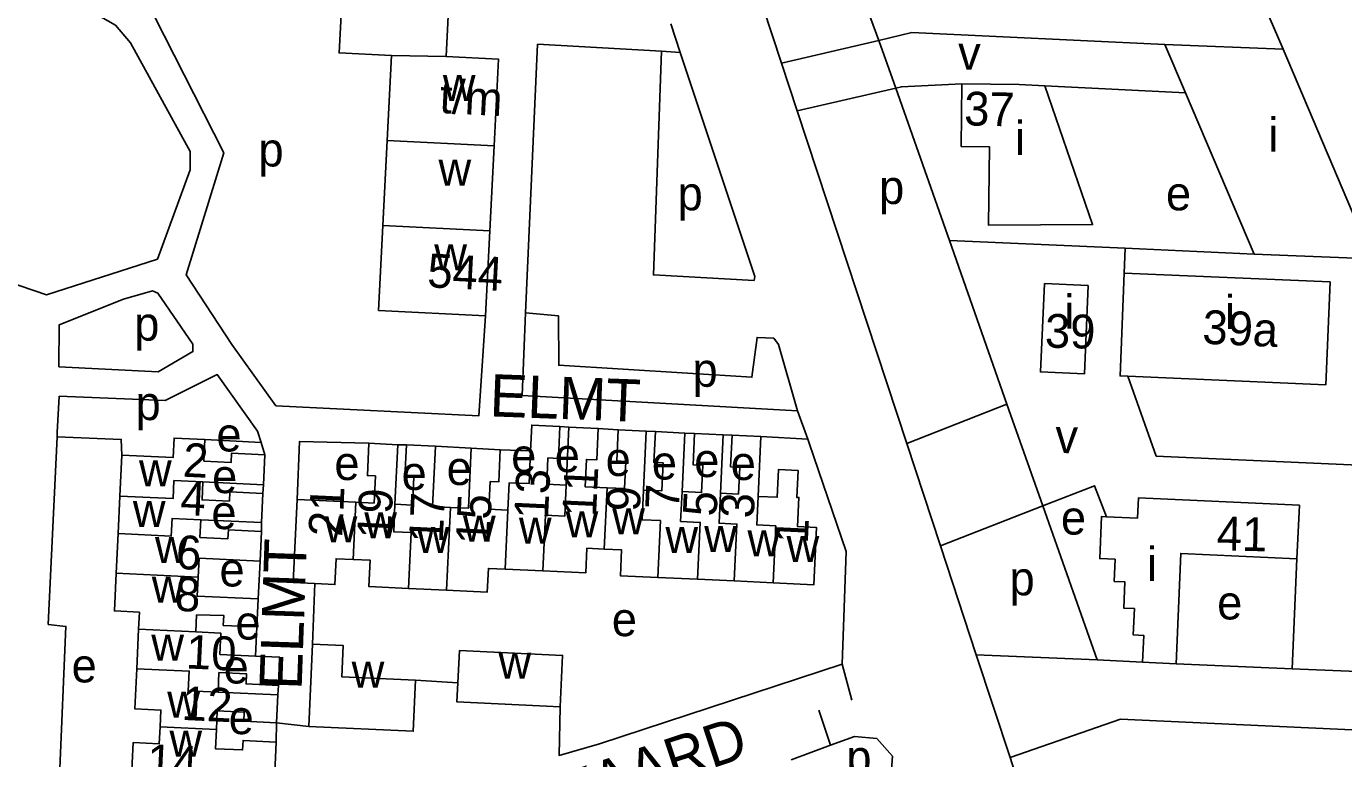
# Model space of a CAD drawing. Extents: x 163026 to 166241, y 382475 to 384501.
# Drawn here: x 164720.8 to 164876.6, y 383908.9 to 383995.6 of the extents above; entities that cross this region are included whole.
import ezdxf

# ---------------------------------------------------------------- set-up
doc = ezdxf.new("R2010")
doc.units = 0
for name, color, linetype in [('BLT_Basislijn', 7, 'Continuous'), ('BLT_Bebouwing', 7, 'Continuous'), ('BLT_Centroide', 7, 'Continuous'), ('BLT_Huisnummer', 7, 'Continuous'), ('BLT_Huisnummer_ tussenligend', 7, 'Continuous'), ('BLT_Huisnummer_reeks', 7, 'Continuous'), ('BLT_Onderverdeling_panden', 7, 'Continuous'), ('BLT_Straatnaam', 7, 'Continuous')]:
    doc.layers.add(name, color=color, linetype=linetype)

msp = doc.modelspace()

# ---------------------------------------------------------------- linework, layer by layer
at = {"layer": 'BLT_Basislijn'}
for p, q in [((164821.62, 383993.91), (164814.91, 384012.33)), ((164869.4, 383992.88), (164861.88, 384010.26)), ((164797, 383995.86), (164798.12, 383992.49)), ((164821.62, 383993.91), (164810.1, 383991.21)), ((164821.62, 383993.91), (164823.61, 383988.26)), ((164795.92, 383992.62), (164798.12, 383992.49)), ((164811.96, 383985.56), (164823.61, 383988.26)), ((164823.61, 383988.26), (164829.95, 383970.22)), ((164841.23, 383988.53), (164857.86, 383987.7)), ((164829.95, 383970.22), (164836.76, 383950.87)), ((164829.95, 383970.22), (164850.73, 383969.31)), ((164850.61, 383966.35), (164850.73, 383969.31)), ((164850.73, 383969.31), (164866, 383968.63)), ((164854.39, 383944.72), (164851.07, 383954.18)), ((164812.01, 383950.1), (164813.21, 383946.73)), ((164824.91, 383946.22), (164836.76, 383950.87)), ((164836.76, 383950.87), (164840.99, 383938.84)), ((164783.9, 383948.24), (164784.96, 383948.17)), ((164788.43, 383948.01), (164790.8, 383947.85)), ((164794.12, 383947.69), (164795.19, 383947.62)), ((164798.67, 383947.46), (164799.82, 383947.42)), ((164803.21, 383947.26), (164804.26, 383947.2)), ((164807.66, 383947.04), (164813.21, 383946.73)), ((164748.58, 383946.34), (164741.93, 383946.7)), ((164749.02, 383944.89), (164748.58, 383946.34)), ((164764.73, 383946.08), (164765.75, 383946.06)), ((164769.19, 383945.9), (164773.41, 383945.65)), ((164776.85, 383945.49), (164780.43, 383945.34)), ((164854.39, 383944.72), (164882.61, 383943.48)), ((164748.79, 383940.3), (164748.86, 383941.35)), ((164840.99, 383938.84), (164847.41, 383920.61)), ((164748.61, 383935.83), (164748.63, 383936.86)), ((164748.21, 383927.85), (164748.45, 383932.31)), ((164871.05, 383932.59), (164870.47, 383919.57)), ((164754.92, 383929.66), (164754.67, 383922.48)), ((164747.92, 383921.07), (164748.05, 383924.53)), ((164833.13, 383921.24), (164837.14, 383909.08)), ((164833.13, 383921.24), (164847.41, 383920.61)), ((164847.41, 383920.61), (164852.77, 383920.36)), ((164818.43, 383915.84), (164817.26, 383920.1)), ((164856.77, 383920.16), (164870.47, 383919.57)), ((164870.47, 383919.57), (164881.54, 383919.1)), ((164750.57, 383916.48), (164750.62, 383917.6)), ((164771.84, 383917.89), (164766.84, 383918.21)), ((164814.52, 383914.69), (164815.88, 383910.53)), ((164750.4, 383913.19), (164750.35, 383910.91)), ((164754.23, 383912.76), (164750.4, 383913.19)), ((164811.26, 383908.79), (164815.88, 383910.53)), ((164837.14, 383909.08), (164837.63, 383907.58))]:
    msp.add_line(p, q, dxfattribs=at)
for points in [[(164799.94, 384021.82), (164801.3, 384017.93), (164810.1, 383991.21)], [(164759.15, 384019.84), (164746.79, 384020.58), (164746.25, 384009.94), (164735.95, 383996.81), (164744.18, 383980.62), (164739.71, 383966.18), (164745.12, 383957.93), (164750.33, 383950.67), (164774.32, 383949.51), (164775.11, 383961.33)], [(164674.71, 383976.23), (164696.78, 383972.86), (164700, 383971.75), (164723.21, 383963.81), (164736.31, 383968.03), (164740.19, 383978.61), (164740.19, 383980.78), (164733.12, 383993.62), (164731.37, 383995.69), (164723.51, 384000.21), (164699.95, 384004.23), (164696.08, 384004.86), (164679.74, 384002.01)], [(164855.42, 383993.42), (164825.52, 383994.83), (164821.62, 383993.91)], [(164795.92, 383992.62), (164781.27, 383993.45), (164779.84, 383961.69)], [(164795.92, 383992.62), (164794.95, 383966.17), (164806.87, 383965.52), (164806.95, 383965.96), (164798.12, 383992.49)], [(164810.1, 383991.21), (164811.96, 383985.56)], [(164831.42, 383988.76), (164824.28, 383988.42), (164823.61, 383988.26)], [(164811.96, 383985.56), (164824.91, 383946.22)], [(164732.31, 383963.29), (164724.69, 383960.24), (164724.67, 383955.29), (164736.41, 383954.68), (164740.51, 383957.1), (164740.51, 383957.99), (164736.37, 383964.01), (164735.73, 383964.26), (164732.31, 383963.29)], [(164779.84, 383961.69), (164779.46, 383951.9), (164812.01, 383950.1)], [(164779.84, 383961.69), (164783.74, 383961.31), (164783.77, 383955.48), (164806.6, 383954.06), (164807.22, 383958.76), (164809.18, 383958.68), (164809.76, 383957.93), (164812.01, 383950.1)], [(164748.58, 383946.34), (164748.16, 383947.69), (164743.38, 383954.38), (164737.23, 383951.3), (164724.71, 383951.81), (164724.48, 383947.54), (164724.46, 383947)], [(164724.46, 383947), (164723.41, 383924.81), (164725.5, 383924.59), (164724.72, 383906.83), (164724.61, 383905.61), (164722.03, 383905.35), (164721.3, 383888.39)], [(164732.09, 383944.85), (164732.04, 383946.71), (164724.46, 383947)], [(164752.84, 383939.6), (164753.1, 383946.45), (164761.33, 383946.24)], [(164813.21, 383946.73), (164813.38, 383946.26), (164817.74, 383933.46), (164817.26, 383920.1)], [(164824.91, 383946.22), (164828.9, 383934.1)], [(164840.99, 383938.84), (164847.09, 383941.23), (164848.52, 383937.56)], [(164828.9, 383934.1), (164840.99, 383938.84)], [(164828.9, 383934.1), (164833.13, 383921.24)], [(164783.93, 383915.08), (164783.81, 383909.32), (164788.58, 383910.69), (164817.26, 383920.1)], [(164837.14, 383909.08), (164850.19, 383913.61), (164904.06, 383911.12)], [(164822.9, 383904.89), (164823.21, 383909.24), (164821.39, 383911.31), (164818.74, 383911.55), (164815.88, 383910.53)]]:
    msp.add_lwpolyline(points, dxfattribs=at)
at = {"layer": 'BLT_Bebouwing'}
for p, q in [((164763.99, 383992.1), (164763.48, 383982.06)), ((164855.42, 383993.42), (164869.4, 383992.88)), ((164857.86, 383987.7), (164855.42, 383993.42)), ((164869.4, 383992.88), (164879.93, 383968.06)), ((164866, 383968.63), (164857.86, 383987.7)), ((164763.48, 383982.06), (164762.97, 383972.02)), ((164775.62, 383971.38), (164776.13, 383981.42)), ((164775.11, 383961.33), (164775.62, 383971.38)), ((164879.93, 383968.06), (164866, 383968.63)), ((164788.43, 383948.01), (164784.96, 383948.17)), ((164794.12, 383947.69), (164790.8, 383947.85)), ((164798.67, 383947.46), (164795.19, 383947.62)), ((164803.21, 383947.26), (164799.82, 383947.42)), ((164807.66, 383947.04), (164804.26, 383947.2)), ((164764.73, 383946.08), (164761.33, 383946.24)), ((164769.19, 383945.9), (164765.75, 383946.06)), ((164776.85, 383945.49), (164773.41, 383945.65)), ((164731.87, 383940), (164732.09, 383944.85)), ((164749.02, 383944.89), (164748.86, 383941.35)), ((164731.66, 383935.56), (164731.87, 383940)), ((164748.79, 383940.3), (164748.63, 383936.86)), ((164759.77, 383939.27), (164752.84, 383939.6)), ((164731.44, 383930.87), (164731.66, 383935.56)), ((164748.61, 383935.83), (164748.45, 383932.31)), ((164777.43, 383931.36), (164781.87, 383931.15)), ((164795.47, 383930.38), (164800.19, 383930.16)), ((164800.19, 383930.16), (164804.52, 383929.96)), ((164804.52, 383929.96), (164809.11, 383929.74)), ((164766, 383929.07), (164770.51, 383928.86)), ((164748.21, 383927.85), (164748.05, 383924.53)), ((164734.09, 383924.24), (164734.18, 383926.28)), ((164733.87, 383919.58), (164734.09, 383924.24)), ((164754.67, 383922.48), (164754.23, 383912.76)), ((164852.77, 383920.36), (164856.77, 383920.16)), ((164750.57, 383916.48), (164750.4, 383913.19)), ((164750.35, 383910.91), (164750.18, 383907.3))]:
    msp.add_line(p, q, dxfattribs=at)
for points in [[(164763.99, 383992.1), (164757.8, 383992.42), (164758.18, 384000), (164758.13, 384000.73), (164758.17, 384001.56)], [(164770.44, 383991.99), (164770.85, 384000), (164770.9, 384000.93)], [(164776.13, 383981.42), (164776.65, 383991.67), (164770.44, 383991.99)], [(164831.42, 383988.76), (164831.33, 383981.36), (164834.71, 383981.31), (164834.59, 383972.04), (164846.88, 383972.12), (164841.23, 383988.53)], [(164841.23, 383988.53), (164838.2, 383988.68), (164831.42, 383988.76)], [(164762.97, 383972.02), (164762.46, 383961.97), (164775.11, 383961.33)], [(164851.07, 383954.18), (164850.13, 383954.22), (164850.61, 383966.35)], [(164850.61, 383966.35), (164874.97, 383965.33), (164874.46, 383953.17), (164851.07, 383954.18)], [(164846.37, 383964.92), (164845.92, 383954.46), (164840.72, 383954.68), (164841.21, 383965.13), (164846.37, 383964.92)], [(164783.9, 383948.24), (164780.58, 383948.39), (164780.43, 383945.34)], [(164784.64, 383941.29), (164782.34, 383941.4), (164782.49, 383944.51), (164783.73, 383944.46), (164783.9, 383948.24)], [(164784.96, 383948.17), (164784.64, 383941.29)], [(164789.48, 383940.99), (164786.88, 383941.11), (164787.03, 383944.33), (164788.26, 383944.28), (164788.43, 383948.01)], [(164790.8, 383947.85), (164790.63, 383944.16), (164791.68, 383944.11), (164791.54, 383940.9), (164789.48, 383940.99)], [(164793.8, 383940.71), (164794.12, 383947.69)], [(164795.19, 383947.62), (164795.02, 383943.97), (164796.1, 383943.92), (164795.95, 383940.61), (164793.8, 383940.71)], [(164798.35, 383940.53), (164798.67, 383947.46)], [(164799.82, 383947.42), (164799.64, 383943.7), (164800.81, 383943.65), (164800.66, 383940.42), (164798.35, 383940.53)], [(164802.89, 383940.34), (164803.21, 383947.26)], [(164804.26, 383947.2), (164804.08, 383943.46), (164805.16, 383943.41), (164805.01, 383940.24), (164802.89, 383940.34)], [(164807.33, 383939.97), (164807.66, 383947.04)], [(164732.09, 383944.85), (164738.19, 383944.57), (164738.29, 383946.87), (164741.93, 383946.7)], [(164741.93, 383946.7), (164741.81, 383944.14), (164745.04, 383943.99), (164745.09, 383945.08), (164749.02, 383944.89)], [(164761.33, 383946.24), (164761.15, 383942.43), (164762.09, 383942.38), (164761.93, 383939.17), (164759.77, 383939.27)], [(164764.4, 383939.03), (164764.73, 383946.08)], [(164765.75, 383946.06), (164765.57, 383942.28), (164766.62, 383942.23), (164766.46, 383938.93), (164764.4, 383939.03)], [(164770.97, 383938.66), (164768.85, 383938.76), (164769.19, 383945.9)], [(164773.41, 383945.65), (164773.08, 383938.56), (164770.97, 383938.66)], [(164777.76, 383938.34), (164775.51, 383938.44), (164775.66, 383941.72), (164776.67, 383941.67), (164776.85, 383945.49)], [(164780.43, 383945.34), (164780.25, 383941.47), (164777.91, 383941.58), (164777.76, 383938.34)], [(164809.11, 383929.74), (164813.93, 383929.52), (164814.25, 383936.28), (164812, 383936.39), (164812.17, 383939.84), (164811.91, 383939.85), (164812.06, 383943.03), (164809.74, 383943.14), (164809.59, 383939.87), (164807.33, 383939.97)], [(164741.69, 383941.68), (164741.59, 383939.55), (164744.82, 383939.4), (164744.87, 383940.49), (164748.79, 383940.3)], [(164748.86, 383941.35), (164741.69, 383941.68)], [(164752.84, 383939.6), (164752.38, 383929.77), (164754.92, 383929.66)], [(164871.33, 383938.94), (164852.32, 383939.81), (164852.21, 383937.4), (164848.52, 383937.56)], [(164848.52, 383937.56), (164847.95, 383937.59), (164847.73, 383932.61), (164849.55, 383932.53), (164849.44, 383929.9), (164850.7, 383929.85), (164850.57, 383926.75), (164851.82, 383926.69), (164851.69, 383923.57), (164852.94, 383923.52), (164852.77, 383920.36)], [(164871.05, 383932.59), (164871.33, 383938.94)], [(164741.44, 383937.2), (164741.34, 383935.11), (164744.66, 383934.96), (164744.71, 383936.02), (164748.61, 383935.83)], [(164748.63, 383936.86), (164741.44, 383937.2)], [(164781.87, 383931.15), (164786.95, 383930.92), (164787.09, 383933.83), (164789.14, 383933.73)], [(164789.14, 383933.73), (164791.19, 383933.64), (164791.05, 383930.58), (164795.47, 383930.38)], [(164856.77, 383920.16), (164857.31, 383933.21), (164871.05, 383932.59)], [(164748.45, 383932.31), (164741.24, 383932.65), (164741.13, 383930.42)], [(164754.92, 383929.66), (164757.3, 383929.54), (164757.44, 383932.59), (164759.45, 383932.5)], [(164759.45, 383932.5), (164761.47, 383932.41), (164761.32, 383929.29), (164766, 383929.07)], [(164770.51, 383928.86), (164775.32, 383928.64), (164775.45, 383931.45), (164777.43, 383931.36)], [(164734.18, 383926.28), (164731.23, 383926.41), (164731.44, 383930.87)], [(164741.13, 383930.42), (164741.03, 383928.18), (164748.21, 383927.85)], [(164740.93, 383925.96), (164740.84, 383923.93)], [(164748.05, 383924.53), (164744.1, 383924.71), (164744.16, 383925.89), (164740.93, 383925.96)], [(164740.84, 383923.93), (164743.82, 383923.78), (164743.7, 383921.27), (164747.92, 383921.07)], [(164766.84, 383918.21), (164758.11, 383918.62), (164758.28, 383922.32), (164754.67, 383922.48)], [(164747.92, 383921.07), (164750.78, 383920.93), (164750.62, 383917.6)], [(164771.84, 383917.89), (164772.02, 383921.72), (164784.21, 383921.15), (164783.93, 383915.08)], [(164736.64, 383912.69), (164736.73, 383914.68), (164733.65, 383914.83), (164733.87, 383919.58)], [(164743.59, 383919.13), (164743.48, 383916.81)], [(164750.62, 383917.6), (164746.79, 383917.78), (164746.84, 383918.98), (164743.59, 383919.13)], [(164754.23, 383912.76), (164766.56, 383912.18), (164766.84, 383918.21)], [(164783.93, 383915.08), (164771.73, 383915.65), (164771.84, 383917.89)], [(164743.48, 383916.81), (164750.57, 383916.48)], [(164750.4, 383913.19), (164746.54, 383913.37), (164746.59, 383914.45), (164743.39, 383914.6), (164743.29, 383912.38)], [(164733.22, 383905.97), (164733.45, 383910.84), (164736.54, 383910.7), (164736.64, 383912.69)], [(164743.29, 383912.38), (164743.18, 383910.12), (164746.38, 383909.97), (164746.44, 383911.09), (164750.35, 383910.91)]]:
    msp.add_lwpolyline(points, dxfattribs=at)
at = {"layer": 'BLT_Onderverdeling_panden'}
for p, q in [((164763.99, 383992.1), (164770.44, 383991.99)), ((164776.13, 383981.42), (164763.48, 383982.06)), ((164775.62, 383971.38), (164762.97, 383972.02)), ((164789.14, 383933.73), (164789.48, 383940.99)), ((164759.45, 383932.5), (164759.77, 383939.27)), ((164770.97, 383938.66), (164770.51, 383928.86)), ((164777.76, 383938.34), (164777.43, 383931.36)), ((164741.13, 383930.42), (164731.44, 383930.87)), ((164740.84, 383923.93), (164734.09, 383924.24)), ((164736.64, 383912.69), (164743.29, 383912.38))]:
    msp.add_line(p, q, dxfattribs=at)
for points in [[(164741.69, 383941.68), (164738.26, 383941.84), (164738.16, 383939.71), (164731.87, 383940)], [(164784.64, 383941.29), (164784.47, 383937.64), (164782.18, 383937.75), (164781.87, 383931.15)], [(164793.8, 383940.71), (164793.64, 383937.21), (164795.78, 383937.11), (164795.47, 383930.38)], [(164798.35, 383940.53), (164798.18, 383937), (164800.5, 383936.89), (164800.19, 383930.16)], [(164802.89, 383940.34), (164802.72, 383936.79), (164804.84, 383936.69), (164804.52, 383929.96)], [(164807.33, 383939.97), (164807.17, 383936.58), (164809.43, 383936.47), (164809.11, 383929.74)], [(164764.4, 383939.03), (164764.25, 383935.78), (164766.31, 383935.68), (164766, 383929.07)], [(164741.44, 383937.2), (164738.05, 383937.36), (164737.95, 383935.27), (164731.66, 383935.56)], [(164743.48, 383916.81), (164739.96, 383916.97), (164740.07, 383919.29), (164733.87, 383919.58)]]:
    msp.add_lwpolyline(points, dxfattribs=at)

# ---------------------------------------------------------------- texts
at = {"layer": 'BLT_Centroide'}
for p in [(164830.94, 383990.45), (164842.45, 383945.1)]:
    msp.add_text('v', height=4, rotation=359, dxfattribs=at).set_placement(p)
for s, p in [('w', (164770.06, 383986.75)), ('i', (164837.72, 383980.34)), ('i', (164867.67, 383980.75)), ('p', (164748.26, 383978.99)), ('w', (164769.55, 383976.72)), ('p', (164797.82, 383973.8)), ('p', (164821.64, 383974.55)), ('e', (164855.56, 383973.8)), ('w', (164769.05, 383966.69)), ('i', (164843.55, 383959.8)), ('i', (164862.54, 383959.75)), ('p', (164733.57, 383958.39)), ('p', (164799.58, 383952.93)), ('p', (164733.73, 383948.99)), ('e', (164743.29, 383945.28)), ('e', (164778.14, 383942.79)), ('e', (164783.29, 383942.84)), ('e', (164789.31, 383942.38)), ('e', (164799.78, 383942.25)), ('w', (164734.14, 383941.15)), ('e', (164757.24, 383941.9)), ('e', (164765.18, 383940.72)), ('e', (164770.51, 383941.31)), ('e', (164794.77, 383941.96)), ('e', (164804.1, 383941.9)), ('e', (164742.78, 383940.35)), ('w', (164733.41, 383936.36)), ('e', (164742.7, 383936.09)), ('w', (164756.08, 383934.52)), ('w', (164760.77, 383935.02)), ('w', (164772.44, 383934.61)), ('w', (164784.57, 383935.12)), ('w', (164790.09, 383935.48)), ('e', (164843.14, 383935.45)), ('w', (164766.98, 383933.28)), ('w', (164779.06, 383934.38)), ('w', (164796.38, 383933.28)), ('w', (164800.97, 383933.37)), ('w', (164736.03, 383932.07)), ('w', (164806.08, 383932.87)), ('w', (164810.7, 383932.21)), ('i', (164853.3, 383929.97)), ('e', (164743.65, 383929.31)), ('p', (164837.06, 383928.26)), ('w', (164735.65, 383927.41)), ('e', (164861.61, 383925.41)), ('e', (164745.54, 383923.03)), ('e', (164790.04, 383923.43)), ('w', (164735.59, 383920.53)), ('e', (164726.17, 383917.96)), ('e', (164744.14, 383917.83)), ('w', (164776.64, 383918.41)), ('w', (164759.28, 383917.34)), ('w', (164737.48, 383913.78)), ('e', (164744.74, 383911.84)), ('w', (164737.74, 383909.19)), ('p', (164817.77, 383907.12))]:
    msp.add_text(s, height=4, dxfattribs=at).set_placement(p)
at = {"layer": 'BLT_Huisnummer'}
for s, rotation, p in [('37', 358.6294, (164831.67, 383983.86)), ('39', 358.6294, (164841.22, 383957.57)), ('39a', 357.474, (164859.81, 383958.03)), ('2', 357.31, (164739.27, 383942.3)), ('13', 87.3268, (164782.49, 383937.2)), ('21', 87.3268, (164758.16, 383935.14)), ('9', 87.3268, (164793.35, 383938.11)), ('17', 87.3268, (164770.04, 383934.38)), ('5', 87.3268, (164802.42, 383937.54)), ('1', 87.3268, (164813.21, 383934.33)), ('41', 358.6294, (164861.53, 383933.6)), ('6', 357.31, (164738.44, 383931.4)), ('10', 357.31, (164739.63, 383919.62)), ('14', 357.31, (164735.02, 383906.67))]:
    msp.add_text(s, height=4, rotation=rotation, dxfattribs=at).set_placement(p)
at = {"layer": 'BLT_Huisnummer_ tussenligend'}
for s, rotation, p in [('11', 87.3268, (164788.17, 383937.48)), ('4', 357.31, (164738.97, 383937.79)), ('19', 87.3268, (164763.9, 383934.87)), ('7', 87.3268, (164797.97, 383938.33)), ('15', 87.3268, (164775.58, 383934.2)), ('3', 87.3268, (164806.82, 383937.32)), ('8', 357.31, (164738.34, 383926.44)), ('12', 357.31, (164739.13, 383913.53))]:
    msp.add_text(s, height=4, rotation=rotation, dxfattribs=at).set_placement(p)
at = {"layer": 'BLT_Huisnummer_reeks'}
for s, rotation, p in [('t/m', 357.0992, (164769.61, 383985.32)), ('544', 357.0994, (164768.16, 383964.71))]:
    msp.add_text(s, height=4, rotation=rotation, dxfattribs=at).set_placement(p)
at = {"layer": 'BLT_Straatnaam'}
for s, rotation, p in [('ELMT', 357.858, (164775.54, 383949.44)), ('ELMT', 87.9874, (164753.36, 383917.03)), ('BUYAARD', 18.2583, (164775.73, 383899.15))]:
    msp.add_text(s, height=5, rotation=rotation, dxfattribs=at).set_placement(p)

doc.saveas('drawing.dxf')
